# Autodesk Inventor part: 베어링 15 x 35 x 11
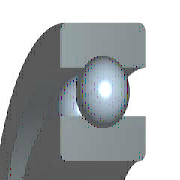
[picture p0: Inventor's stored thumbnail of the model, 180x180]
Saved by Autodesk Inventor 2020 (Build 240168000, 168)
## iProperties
Created: 2012-02
Part Number: 베어링 15 x 35 x 11
Material: 강철, 연강
Description: 깊은 그루브 볼 베어링
Document SubType Name: Modeling
Standard: KS B 2023
Designer: mduedu
Standards Organization: KS
Language: ko-KR
Size Designation: 6202 - 15 x 35 x 11
Categories: <MemberInstance><Categories><Category DisplayName="샤프트 부품" InternalName="7f7aeb1f-a693-4053-b835-cee3144e0d98" Mnemonic="SHFT"><Category DisplayName="베어링" Inter
Density: 1 g/cm^3
Appearance: 밝은 황색
IsCustomPart: 1
Author: mduedu
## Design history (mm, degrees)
sketch "스케치" dims "d0" = 5.2 (= -0.26 x WD + 0.26 x BD)
  geometry: L1 (2.9, 12.5)-(8.1, 12.5); L2 (5.5, 12.5)-(5.5, 9.9); L3 (5.5, 12.5)-(5.5, 15.1); L4 (3.568, 10.76)-(0, 10.76); L5 (0, 7.5)-(11, 7.5); L6 (3.568, 14.24)-(0, 14.24); L7 (0, 17.5)-(11, 17.5); L8 (11, 7.5)-(11, 10.76); L9 (7.432, 10.76)-(11, 10.76); L10 (7.432, 14.24)-(11, 14.24); L11 (11, 17.5)-(11, 14.24); L12 (-1.4, 0)-(8.4, 0) reference; L13 (0, -0.3)-(0, 5.3) reference
  constraints: 22 end point, 4 point on line, 2 collinear, 2 perpendicular, 2 symmetric about line, 1 midpoint, 1 parallel, 14 other
  dimensions: "d9" = 15 diameter of L5 L12 (= WD); "d11" = 35 diameter of L7 L12 (= BD); "d12" = 11 distance between parallel lines of L8 L13 (= KB); "d13" = 21.52 diameter of L9 L12 (= 0.326 x BD + 0.674 x WD)
revolve "본체" stored, may be unused: angle "d6" = 90 deg
revolve "볼" stored, may be unused: angle "d7" = 90 deg
pattern_circular "IDS_ARRAYBALL[SIMPL:T]" dims angle "d3" = 360 deg
body "Solid1"
fillet "모깎기1" dims "d1" = 0.6 (= KRS)
other parameters: "WD" = 15 [user parameter; used in 5 equation terms], "BD" = 35 [user parameter; used in 5 equation terms], "KB" = 11 [user parameter; used in 1 equation term], "KRS" = 0.6 [user parameter; used in 1 equation term], "d4" = 0, "d5" = 0, "d8" = 0, "d14" = 0, "d15" = 0, "BBA" = 0 [user parameter], "BC0" = 3750000 [user parameter], "BC" = 7800000 [user parameter], "BR" = 17.5 (= 0.5 x BD) [user parameter], "WR" = 7.5 (= 0.5 x WD) [user parameter]
